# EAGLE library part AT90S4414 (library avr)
MICROCONTROLLER 4 Kbytes FLASH 256 bytes SRAM 256 bytes EEPROM UART
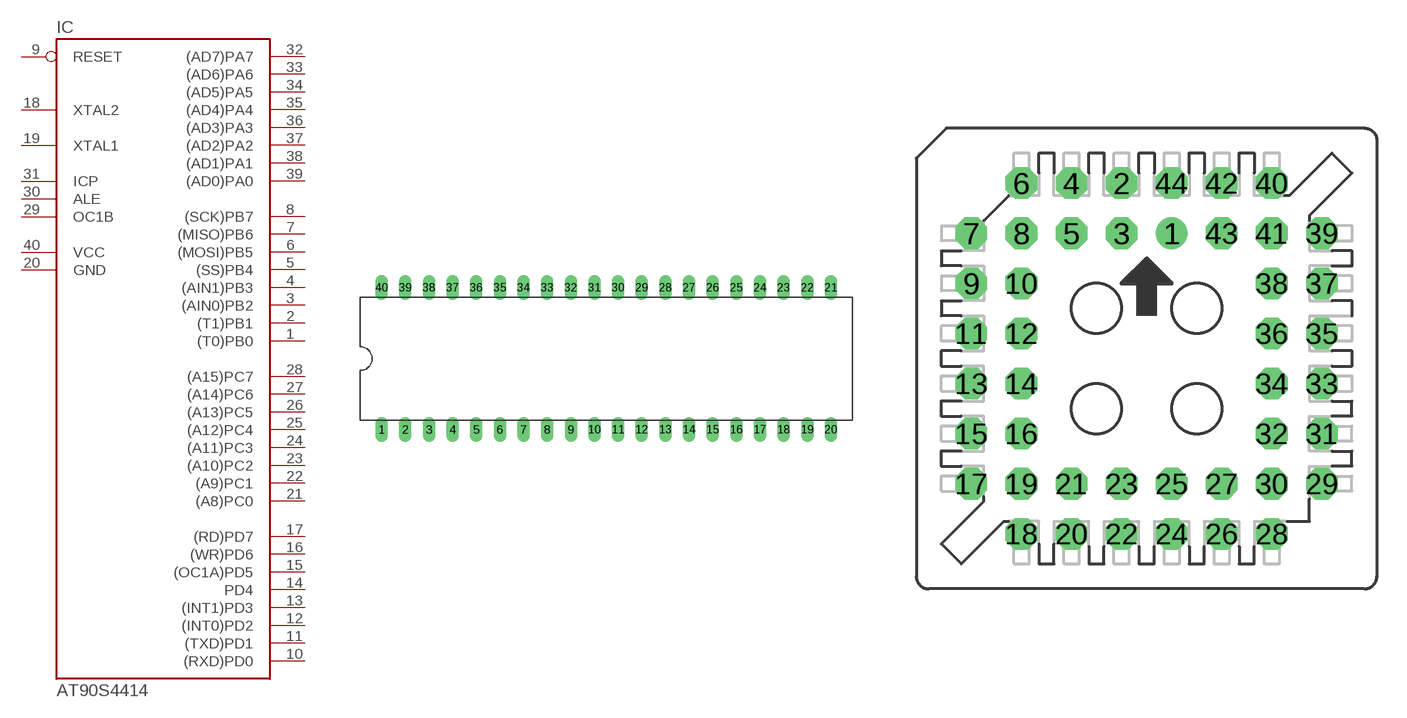
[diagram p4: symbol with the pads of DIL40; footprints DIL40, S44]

Designator prefix IC

## AT90S4414P  [DIL40]
1  (T0)PB0
2  (T1)PB1
3  (AIN0)PB2
4  (AIN1)PB3
5  (SS)PB4
6  (MOSI)PB5
7  (MISO)PB6
8  (SCK)PB7
9  RESET  in
10  (RXD)PD0
11  (TXD)PD1
12  (INT0)PD2
13  (INT1)PD3
14  PD4
15  (OC1A)PD5
16  (WR)PD6
17  (RD)PD7
18  XTAL2
19  XTAL1
20  GND  pwr
21  (A8)PC0
22  (A9)PC1
23  (A10)PC2
24  (A11)PC3
25  (A12)PC4
26  (A13)PC5
27  (A14)PC6
28  (A15)PC7
29  OC1B
30  ALE
31  ICP
32  (AD7)PA7
33  (AD6)PA6
34  (AD5)PA5
35  (AD4)PA4
36  (AD3)PA3
37  (AD2)PA2
38  (AD1)PA1
39  (AD0)PA0
40  VCC  pwr

## AT90S4414J1  [S44]
2  (T0)PB0
3  (T1)PB1
4  (AIN0)PB2
5  (AIN1)PB3
6  (SS)PB4
7  (MOSI)PB5
8  (MISO)PB6
9  (SCK)PB7
10  RESET  in
11  (RXD)PD0
13  (TXD)PD1
14  (INT0)PD2
15  (INT1)PD3
16  PD4
17  (OC1A)PD5
18  (WR)PD6
19  (RD)PD7
20  XTAL2
21  XTAL1
22  GND  pwr
24  (A8)PC0
25  (A9)PC1
26  (A10)PC2
27  (A11)PC3
28  (A12)PC4
29  (A13)PC5
30  (A14)PC6
31  (A15)PC7
32  OC1B
33  ALE
35  ICP
36  (AD7)PA7
37  (AD6)PA6
38  (AD5)PA5
39  (AD4)PA4
40  (AD3)PA3
41  (AD2)PA2
42  (AD1)PA1
43  (AD0)PA0
44  VCC  pwr

## AT90S4414J2  [PLCC44]
Pads as for S44

## AT90S4414J3  [PLCC-SM44]
Pads as for S44

## AT90S4414A  [TQFP44]
1  (MOSI)PB5
2  (MISO)PB6
3  (SCK)PB7
4  RESET  in
5  (RXD)PD0
7  (TXD)PD1
8  (INT0)PD2
9  (INT1)PD3
10  PD4
11  (OC1A)PD5
12  (WR)PD6
13  (RD)PD7
14  XTAL2
15  XTAL1
16  GND  pwr
18  (A8)PC0
19  (A9)PC1
20  (A10)PC2
21  (A11)PC3
22  (A12)PC4
23  (A13)PC5
24  (A14)PC6
25  (A15)PC7
26  OC1B
27  ALE
29  ICP
30  (AD7)PA7
31  (AD6)PA6
32  (AD5)PA5
33  (AD4)PA4
34  (AD3)PA3
35  (AD2)PA2
36  (AD1)PA1
37  (AD0)PA0
38  VCC  pwr
40  (T0)PB0
41  (T1)PB1
42  (AIN0)PB2
43  (AIN1)PB3
44  (SS)PB4

## Footprint DIL40 (pad centres in mm)
Dual In Line
drill 0.813 long: 1 -24.13,-7.62; 2 -21.59,-7.62; 3 -19.05,-7.62; 4 -16.51,-7.62; 5 -13.97,-7.62; 6 -11.43,-7.62; 7 -8.89,-7.62; 8 -6.35,-7.62; 9 -3.81,-7.62; 10 -1.27,-7.62; 11 1.27,-7.62; 12 3.81,-7.62; 13 6.35,-7.62; 14 8.89,-7.62; 15 11.43,-7.62; 16 13.97,-7.62; 17 16.51,-7.62; 18 19.05,-7.62; 19 21.59,-7.62; 20 24.13,-7.62; 21 24.13,7.62; 22 21.59,7.62; 23 19.05,7.62; 24 16.51,7.62; 25 13.97,7.62; 26 11.43,7.62; 27 8.89,7.62; 28 6.35,7.62; 29 3.81,7.62; 30 1.27,7.62; 31 -1.27,7.62; 32 -3.81,7.62; 33 -6.35,7.62; 34 -8.89,7.62; 35 -11.43,7.62; 36 -13.97,7.62; 37 -16.51,7.62; 38 -19.05,7.62; 39 -21.59,7.62; 40 -24.13,7.62

## Footprint S44 (pad centres in mm)
Throughhole Plastic J-Leaded Chip Carrier Socket
drill 0.813 pad 1.6 round: 1 1.27,6.35
drill 0.813 pad 1.6 octagon: 2 -1.27,8.89; 3 -1.27,6.35; 4 -3.81,8.89; 5 -3.81,6.35; 6 -6.35,8.89; 7 -8.89,6.35; 8 -6.35,6.35; 9 -8.89,3.81; 10 -6.35,3.81; 11 -8.89,1.27; 12 -6.35,1.27; 13 -8.89,-1.27; 14 -6.35,-1.27; 15 -8.89,-3.81; 16 -6.35,-3.81; 17 -8.89,-6.35; 18 -6.35,-8.89; 19 -6.35,-6.35; 20 -3.81,-8.89; 21 -3.81,-6.35; 22 -1.27,-8.89; 23 -1.27,-6.35; 24 1.27,-8.89; 25 1.27,-6.35; 26 3.81,-8.89; 27 3.81,-6.35; 28 6.35,-8.89; 29 8.89,-6.35; 30 6.35,-6.35; 31 8.89,-3.81; 32 6.35,-3.81; 33 8.89,-1.27; 34 6.35,-1.27; 35 8.89,1.27; 36 6.35,1.27; 37 8.89,3.81; 38 6.35,3.81; 39 8.89,6.35; 40 6.35,8.89; 41 6.35,6.35; 42 3.81,8.89; 43 3.81,6.35; 44 1.27,8.89

## Footprint PLCC44 (pad centres in mm)
Plastic J-Leaded Chip Carrier
smd 1.8 x 0.76: 1 -7.86,0; 2 -7.86,-1.27; 3 -7.86,-2.54; 4 -7.86,-3.81; 5 -7.86,-5.08; 6 -7.86,-6.35; 18 7.86,-6.35; 19 7.86,-5.08; 20 7.86,-3.81; 21 7.86,-2.54; 22 7.86,-1.27; 23 7.86,0; 24 7.86,1.27; 25 7.86,2.54; 26 7.86,3.81; 27 7.86,5.08; 28 7.86,6.35; 40 -7.86,6.35; 41 -7.86,5.08; 42 -7.86,3.81; 43 -7.86,2.54; 44 -7.86,1.27
smd 0.76 x 1.8: 7 -6.35,-7.86; 8 -5.08,-7.86; 9 -3.81,-7.86; 10 -2.54,-7.86; 11 -1.27,-7.86; 12 0,-7.86; 13 1.27,-7.86; 14 2.54,-7.86; 15 3.81,-7.86; 16 5.08,-7.86; 17 6.35,-7.86; 29 6.35,7.86; 30 5.08,7.86; 31 3.81,7.86; 32 2.54,7.86; 33 1.27,7.86; 34 0,7.86; 35 -1.27,7.86; 36 -2.54,7.86; 37 -3.81,7.86; 38 -5.08,7.86; 39 -6.35,7.86

## Footprint PLCC-SM44 (pad centres in mm)
SMD Plastic J-Leaded Chip Carrier Socket
smd 2.591 x 0.66: 1 -8.89,0; 2 -8.89,-1.27; 3 -8.89,-2.54; 4 -8.89,-3.81; 5 -8.89,-5.08; 6 -8.89,-6.35; 18 8.89,-6.35; 19 8.89,-5.08; 20 8.89,-3.81; 21 8.89,-2.54; 22 8.89,-1.27; 23 8.89,0; 24 8.89,1.27; 25 8.89,2.54; 26 8.89,3.81; 27 8.89,5.08; 28 8.89,6.35; 40 -8.89,6.35; 41 -8.89,5.08; 42 -8.89,3.81; 43 -8.89,2.54; 44 -8.89,1.27
smd 0.66 x 2.591: 7 -6.35,-8.89; 8 -5.08,-8.89; 9 -3.81,-8.89; 10 -2.54,-8.89; 11 -1.27,-8.89; 12 0,-8.89; 13 1.27,-8.89; 14 2.54,-8.89; 15 3.81,-8.89; 16 5.08,-8.89; 17 6.35,-8.89; 29 6.35,8.89; 30 5.08,8.89; 31 3.81,8.89; 32 2.54,8.89; 33 1.27,8.89; 34 0,9.017; 35 -1.27,8.89; 36 -2.54,8.89; 37 -3.81,8.89; 38 -5.08,8.89; 39 -6.35,8.89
